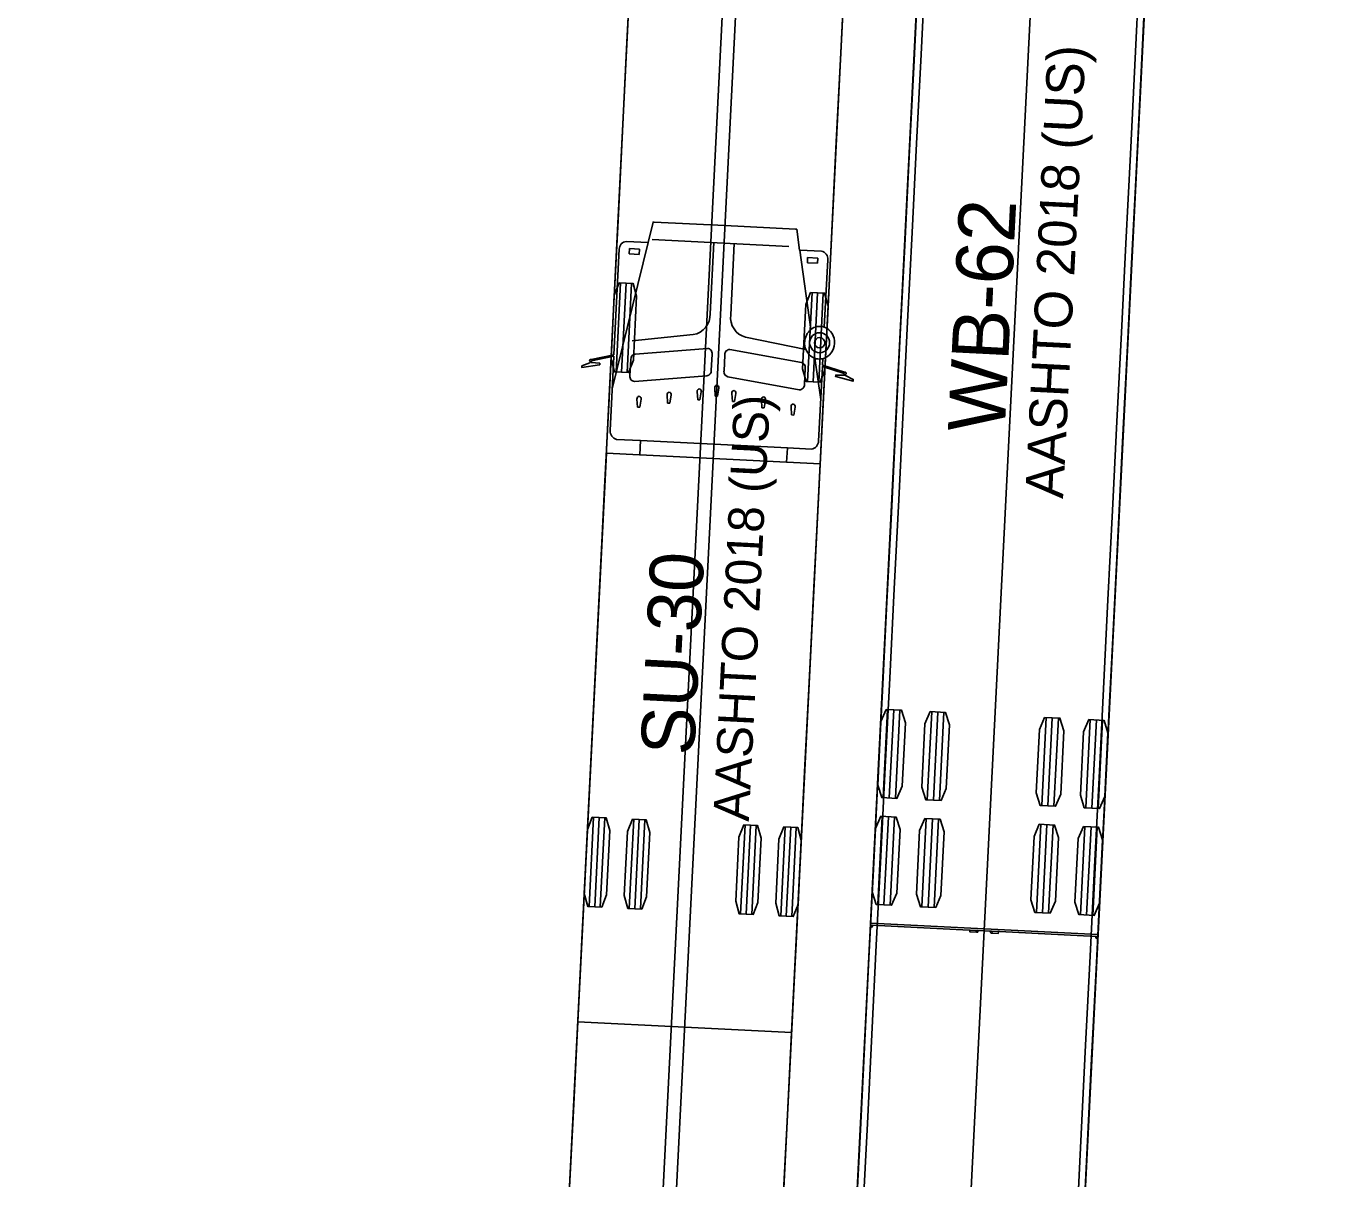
# Model space of a CAD drawing. Extents: x 260275 to 261282, y 610916 to 614143.
# Drawn here: x 261035.48 to 261084.72, y 612370.96 to 612414.03 of the extents above; entities that cross this region are included whole.
import ezdxf

# ---------------------------------------------------------------- set-up
doc = ezdxf.new("R2010")
doc.units = 0
doc.layers.add('GE_X_Alignment', color=7, linetype='Continuous')
doc.layers.add('TopoDOT_Transients', color=7, linetype='Continuous')

msp = doc.modelspace()

# ---------------------------------------------------------------- linework, layer by layer
at = {"layer": 'GE_X_Alignment'}
msp.add_line((260986.249, 610915.954), (261148.276, 614142.838), dxfattribs=at)
at = {"layer": 'TopoDOT_Transients'}
for p, q in [((261059.045, 612136.423), (261081.046, 612574.591)), ((261048.059, 612136.974), (261068.197, 612538.052)), ((261057.385, 612400.477), (261058.725, 612405.944)), ((261058.014, 612405.523), (261058.024, 612405.717)), ((261058.024, 612405.717), (261058.402, 612405.698)), ((261058.402, 612405.698), (261058.392, 612405.504)), ((261063.98, 612405.803), (261058.881, 612406.059)), ((261061.181, 612405.944), (261061.047, 612403.279)), ((261061.946, 612405.905), (261061.812, 612403.241)), ((261058.392, 612405.504), (261058.014, 612405.523)), ((261064.807, 612402.694), (261064.389, 612405.66)), ((261064.686, 612405.383), (261064.676, 612405.189)), ((261064.676, 612405.189), (261065.054, 612405.17)), ((261065.064, 612405.364), (261064.686, 612405.383)), ((261065.054, 612405.17), (261065.064, 612405.364)), ((261065.31, 612402.785), (261065.437, 612405.304)), ((261057.692, 612404.439), (261057.525, 612401.11)), ((261057.9, 612404.428), (261057.733, 612401.099)), ((261058.108, 612404.418), (261057.941, 612401.089)), ((261064.85, 612404.079), (261064.683, 612400.75)), ((261065.058, 612404.069), (261064.891, 612400.74)), ((261065.266, 612404.059), (261065.099, 612400.729)), ((261060.409, 612402.503), (261058.13, 612402.272)), ((261062.369, 612402.405), (261064.625, 612401.944)), ((261058.237, 612401.773), (261060.946, 612401.989)), ((261061.117, 612401.778), (261061.086, 612401.162)), ((261061.592, 612401.754), (261061.561, 612401.138)), ((261064.457, 612401.461), (261061.783, 612401.947)), ((261058.045, 612400.963), (261058.075, 612401.579)), ((261064.567, 612400.635), (261064.598, 612401.251)), ((261065.175, 612400.085), (261064.959, 612401.619)), ((261060.924, 612400.968), (261058.216, 612400.752)), ((261061.702, 612400.929), (261064.376, 612400.443)), ((261060.579, 612400.073), (261060.558, 612400.374)), ((261060.712, 612400.366), (261060.661, 612400.069)), ((261061.235, 612400.208), (261061.214, 612400.509)), ((261061.368, 612400.502), (261061.317, 612400.204)), ((261061.874, 612400.008), (261061.853, 612400.309)), ((261062.007, 612400.301), (261061.956, 612400.004)), ((261058.328, 612399.793), (261058.307, 612400.094)), ((261058.41, 612399.788), (261058.328, 612399.793)), ((261058.461, 612400.086), (261058.41, 612399.788)), ((261059.454, 612399.947), (261059.433, 612400.262)), ((261059.536, 612399.943), (261059.454, 612399.947)), ((261059.587, 612400.254), (261059.536, 612399.943)), ((261060.661, 612400.069), (261060.579, 612400.073)), ((261061.317, 612400.204), (261061.235, 612400.208)), ((261061.956, 612400.004), (261061.874, 612400.008)), ((261062.98, 612399.77), (261062.96, 612400.071)), ((261063.063, 612399.765), (261062.98, 612399.77)), ((261063.114, 612400.063), (261063.063, 612399.765)), ((261064.086, 612399.503), (261064.065, 612399.805)), ((261064.219, 612399.797), (261064.168, 612399.499)), ((261064.168, 612399.499), (261064.086, 612399.503)), ((261063.928, 612398.27), (261058.443, 612398.545)), ((261063.902, 612397.739), (261058.417, 612398.014)), ((261067.676, 612388.494), (261067.51, 612385.199)), ((261067.905, 612388.483), (261067.739, 612385.187)), ((261068.134, 612388.471), (261067.968, 612385.176)), ((261069.324, 612388.412), (261069.158, 612385.116)), ((261069.553, 612388.4), (261069.387, 612385.104)), ((261069.782, 612388.389), (261069.616, 612385.093)), ((261073.602, 612388.197), (261073.436, 612384.901)), ((261073.831, 612388.185), (261073.665, 612384.89)), ((261074.06, 612388.174), (261073.894, 612384.878)), ((261075.25, 612388.114), (261075.084, 612384.818)), ((261075.479, 612388.103), (261075.313, 612384.807)), ((261075.707, 612388.091), (261075.542, 612384.795)), ((261056.689, 612384.464), (261056.522, 612381.135)), ((261056.897, 612384.454), (261056.73, 612381.124)), ((261057.105, 612384.443), (261056.938, 612381.114)), ((261058.187, 612384.389), (261058.02, 612381.06)), ((261058.395, 612384.378), (261058.228, 612381.049)), ((261058.603, 612384.368), (261058.436, 612381.039)), ((261062.349, 612384.18), (261062.182, 612380.851)), ((261062.557, 612384.169), (261062.39, 612380.84)), ((261062.765, 612384.159), (261062.598, 612380.83)), ((261063.847, 612384.105), (261063.68, 612380.775)), ((261064.055, 612384.094), (261063.888, 612380.765)), ((261064.263, 612384.084), (261064.096, 612380.755)), ((261067.475, 612384.499), (261067.31, 612381.204)), ((261067.704, 612384.488), (261067.539, 612381.192)), ((261067.933, 612384.476), (261067.768, 612381.181)), ((261069.123, 612384.417), (261068.958, 612381.121)), ((261069.352, 612384.405), (261069.187, 612381.109)), ((261069.581, 612384.394), (261069.416, 612381.098)), ((261073.401, 612384.202), (261073.236, 612380.906)), ((261073.63, 612384.19), (261073.465, 612380.895)), ((261073.859, 612384.179), (261073.693, 612380.883)), ((261075.049, 612384.119), (261074.884, 612380.823)), ((261075.278, 612384.108), (261075.113, 612380.812)), ((261075.507, 612384.096), (261075.341, 612380.8)), ((261075.535, 612380.081), (261067.045, 612380.507)), ((261071.021, 612380.237), (261070.756, 612380.25)), ((261071.027, 612380.236), (261071.55, 612380.21)), ((261071.287, 612380.224), (261071.29, 612380.294)), ((261071.817, 612380.197), (261071.552, 612380.21))]:
    msp.add_line(p, q, dxfattribs=at)
for points in [[(261051.548, 612071.863), (261074.206, 612523.277)], [(261082.631, 612521.243), (261060.03, 612071.291)], [(261042.767, 612111.356), (261063.016, 612514.614)], [(261070.923, 612512.551), (261050.75, 612110.806)], [(261075.509, 612380.012), (261075.531, 612380.01), (261077.935, 612427.88), (261073.69, 612428.093), (261069.445, 612428.306), (261067.042, 612380.437), (261067.064, 612380.436)], [(261055.762, 612370.162), (261055.93, 612373.49), (261056.097, 612376.819), (261056.264, 612380.147), (261056.431, 612383.476), (261056.598, 612386.804), (261056.765, 612390.132), (261056.932, 612393.461), (261057.099, 612396.789), (261057.267, 612400.118), (261057.434, 612403.446), (261057.601, 612406.775), (261057.768, 612410.103), (261057.935, 612413.432), (261058.102, 612416.76)], [(261055.763, 612370.166), (261055.93, 612373.494), (261056.097, 612376.823), (261056.264, 612380.151), (261056.431, 612383.48), (261056.598, 612386.808), (261056.765, 612390.137), (261056.933, 612393.465), (261057.1, 612396.793), (261057.267, 612400.122), (261057.434, 612403.45), (261057.601, 612406.779), (261057.768, 612410.107), (261057.935, 612413.436), (261058.102, 612416.764)], [(261063.752, 612369.761), (261063.919, 612373.089), (261064.087, 612376.417), (261064.254, 612379.746), (261064.421, 612383.074), (261064.588, 612386.403), (261064.755, 612389.731), (261064.922, 612393.06), (261065.089, 612396.388), (261065.256, 612399.717), (261065.424, 612403.045), (261065.591, 612406.373), (261065.758, 612409.702), (261065.925, 612413.03), (261066.092, 612416.359)], [(261063.753, 612369.765), (261063.92, 612373.093), (261064.087, 612376.422), (261064.254, 612379.75), (261064.421, 612383.079), (261064.588, 612386.407), (261064.755, 612389.735), (261064.922, 612393.064), (261065.09, 612396.392), (261065.257, 612399.721), (261065.424, 612403.049), (261065.591, 612406.378), (261065.758, 612409.706), (261065.925, 612413.035), (261066.092, 612416.363)], [(261066.753, 612369.691), (261066.92, 612373.021), (261067.087, 612376.35), (261067.254, 612379.68), (261067.421, 612383.009), (261067.589, 612386.339), (261067.756, 612389.668), (261067.923, 612392.998), (261068.09, 612396.328), (261068.257, 612399.657), (261068.424, 612402.987), (261068.592, 612406.316), (261068.759, 612409.646), (261068.926, 612412.975), (261069.093, 612416.305)], [(261066.478, 612369.212), (261066.645, 612372.541), (261066.813, 612375.871), (261066.98, 612379.2), (261067.147, 612382.53), (261067.314, 612385.859), (261067.481, 612389.189), (261067.649, 612392.518), (261067.816, 612395.848), (261067.983, 612399.178), (261068.15, 612402.507), (261068.317, 612405.837), (261068.484, 612409.166), (261068.652, 612412.496), (261068.819, 612415.825)], [(261074.743, 612369.29), (261074.91, 612372.62), (261075.077, 612375.949), (261075.244, 612379.279), (261075.411, 612382.608), (261075.578, 612385.938), (261075.746, 612389.267), (261075.913, 612392.597), (261076.08, 612395.926), (261076.247, 612399.256), (261076.414, 612402.585), (261076.582, 612405.915), (261076.749, 612409.245), (261076.916, 612412.574), (261077.083, 612415.904)], [(261074.968, 612368.785), (261075.135, 612372.115), (261075.302, 612375.444), (261075.469, 612378.774), (261075.636, 612382.104), (261075.803, 612385.433), (261075.971, 612388.763), (261076.138, 612392.092), (261076.305, 612395.422), (261076.472, 612398.751), (261076.639, 612402.081), (261076.807, 612405.41), (261076.974, 612408.74), (261077.141, 612412.069), (261077.308, 612415.399)], [(261065.199, 612405.619), (261064.392, 612405.66), (261064.388, 612405.664), (261064.278, 612406.442), (261064.236, 612406.446), (261061.596, 612406.579), (261058.956, 612406.712), (261058.913, 612406.712), (261058.726, 612405.949), (261058.722, 612405.944), (261057.915, 612405.985)], [(261057.647, 612405.695), (261057.449, 612401.767), (261057.442, 612401.755), (261056.6, 612401.571), (261056.599, 612401.571)], [(261056.555, 612401.5), (261056.552, 612401.453), (261056.552, 612401.452), (261056.251, 612401.336), (261056.248, 612401.271), (261056.25, 612401.271), (261056.913, 612401.377), (261056.916, 612401.378), (261056.918, 612401.434), (261056.916, 612401.434), (261056.599, 612401.458), (261056.599, 612401.459), (261056.602, 612401.503)], [(261056.614, 612401.523), (261056.614, 612401.523), (261057.441, 612401.701), (261057.446, 612401.689), (261057.306, 612398.918)], [(261065.097, 612398.527), (261065.236, 612401.298), (261065.241, 612401.309), (261066.046, 612401.049), (261066.047, 612401.049)], [(261066.066, 612401.096), (261066.065, 612401.096), (261065.246, 612401.363), (261065.24, 612401.376), (261065.251, 612401.603)], [(261066.057, 612401.028), (261066.055, 612400.984), (261066.055, 612400.984), (261065.737, 612400.991), (261065.735, 612400.991), (261065.732, 612400.935), (261065.735, 612400.934), (261066.383, 612400.762), (261066.386, 612400.762), (261066.389, 612400.827), (261066.101, 612400.973), (261066.101, 612400.973), (261066.103, 612401.021)], [(261057.545, 612398.59), (261058.44, 612398.545), (261058.443, 612398.541), (261058.417, 612398.015), (261058.406, 612398.015), (261057.164, 612398.077), (261056.097, 612376.817), (261060.092, 612376.617), (261064.087, 612376.416), (261065.154, 612397.676), (261063.913, 612397.738), (261063.902, 612397.74), (261063.928, 612398.266), (261063.931, 612398.27), (261064.826, 612398.225)], [(261067.088, 612380.434), (261067.089, 612380.434), (261070.72, 612380.252), (261070.756, 612380.25), (261070.752, 612380.18), (261070.754, 612380.18), (261071.02, 612380.166)], [(261071.546, 612380.14), (261071.812, 612380.126), (261071.814, 612380.127), (261071.817, 612380.197), (261071.853, 612380.195), (261075.484, 612380.013), (261075.485, 612380.013)]]:
    msp.add_lwpolyline(points, dxfattribs=at)
for points in [[(261057.641, 612404.441), (261058.16, 612404.415), (261058.293, 612403.941), (261058.173, 612401.544), (261057.993, 612401.086), (261057.473, 612401.112), (261057.34, 612401.586), (261057.461, 612403.983)], [(261064.798, 612404.082), (261065.318, 612404.056), (261065.451, 612403.582), (261065.33, 612401.185), (261065.15, 612400.727), (261064.631, 612400.753), (261064.498, 612401.227), (261064.618, 612403.624)], [(261067.619, 612388.497), (261068.19, 612388.469), (261068.339, 612387.999), (261068.22, 612385.626), (261068.025, 612385.173), (261067.454, 612385.201), (261067.305, 612385.671), (261067.424, 612388.044)], [(261069.267, 612388.415), (261069.838, 612388.386), (261069.987, 612387.916), (261069.868, 612385.543), (261069.673, 612385.09), (261069.102, 612385.119), (261068.953, 612385.589), (261069.072, 612387.962)], [(261073.545, 612388.2), (261074.116, 612388.171), (261074.265, 612387.701), (261074.146, 612385.328), (261073.951, 612384.875), (261073.38, 612384.904), (261073.231, 612385.374), (261073.35, 612387.747)], [(261075.193, 612388.117), (261075.764, 612388.088), (261075.913, 612387.618), (261075.794, 612385.245), (261075.599, 612384.792), (261075.027, 612384.821), (261074.879, 612385.291), (261074.998, 612387.664)], [(261056.638, 612384.467), (261057.157, 612384.44), (261057.29, 612383.967), (261057.17, 612381.57), (261056.99, 612381.111), (261056.47, 612381.137), (261056.337, 612381.611), (261056.458, 612384.008)], [(261058.136, 612384.391), (261058.655, 612384.365), (261058.788, 612383.891), (261058.668, 612381.494), (261058.488, 612381.036), (261057.969, 612381.062), (261057.835, 612381.536), (261057.956, 612383.933)], [(261062.297, 612384.182), (261062.816, 612384.156), (261062.95, 612383.682), (261062.829, 612381.285), (261062.649, 612380.827), (261062.13, 612380.853), (261061.997, 612381.327), (261062.117, 612383.724)], [(261063.795, 612384.107), (261064.315, 612384.081), (261064.448, 612383.607), (261064.327, 612381.21), (261064.147, 612380.752), (261063.628, 612380.778), (261063.495, 612381.252), (261063.615, 612383.649)], [(261067.419, 612384.502), (261067.99, 612384.474), (261068.139, 612384.004), (261068.02, 612381.631), (261067.824, 612381.178), (261067.253, 612381.206), (261067.104, 612381.677), (261067.223, 612384.05)], [(261069.067, 612384.42), (261069.638, 612384.391), (261069.787, 612383.921), (261069.668, 612381.548), (261069.472, 612381.095), (261068.901, 612381.124), (261068.752, 612381.594), (261068.871, 612383.967)], [(261073.344, 612384.205), (261073.916, 612384.176), (261074.065, 612383.706), (261073.946, 612381.333), (261073.75, 612380.88), (261073.179, 612380.909), (261073.03, 612381.379), (261073.149, 612383.752)], [(261074.992, 612384.122), (261075.564, 612384.093), (261075.713, 612383.623), (261075.593, 612381.25), (261075.398, 612380.797), (261074.827, 612380.826), (261074.678, 612381.296), (261074.797, 612383.669)]]:
    msp.add_lwpolyline(points, close=True, dxfattribs=at)
for centre, radius in [((261065.136, 612402.201), 0.374), ((261065.136, 612402.201), 0.193), ((261067.074, 612380.401), 0.0266), ((261075.495, 612379.978), 0.0266)]:
    msp.add_circle(centre, radius, dxfattribs=at)
for centre, radius, start, end in [((261057.928, 612405.703), 0.282, 92.6739, 181.7533), ((261065.158, 612405.34), 0.282, 352.4977, 81.5771), ((261060.274, 612403.264), 0.773, 280.016, 1.1001), ((261062.579, 612403.148), 0.773, 173.1509, 254.235), ((261065.14, 612402.287), 0.526, 71.0707, 129.3167), ((261065.069, 612402.205), 0.628, 286.8788, 67.3705), ((261065.205, 612402.206), 0.629, 129.1711, 177.8604), ((261058.268, 612401.583), 0.193, 99.2679, 181.1824), ((261060.934, 612401.805), 0.184, 351.6672, 86.5274), ((261061.776, 612401.763), 0.184, 87.7236, 182.5838), ((261065.204, 612402.191), 0.63, 176.4803, 228.8831), ((261056.578, 612401.535), 0.0418, 59.6174, 236.6324), ((261056.572, 612401.535), 0.0434, 312.5392, 343.212), ((261064.407, 612401.275), 0.193, 353.0686, 74.9831), ((261065.132, 612402.114), 0.524, 229.3845, 283.1846), ((261058.227, 612400.936), 0.184, 171.6617, 266.5329), ((261060.893, 612401.158), 0.193, 279.263, 1.1873), ((261061.752, 612401.115), 0.193, 173.0637, 254.988), ((261066.089, 612401.057), 0.0434, 191.039, 221.7118), ((261066.083, 612401.058), 0.0418, 297.6187, 114.6336), ((261059.523, 612400.262), 0.091, 94.6451, 188.8089), ((261059.499, 612400.263), 0.0909, 345.4064, 79.6416), ((261060.648, 612400.388), 0.091, 94.6451, 188.8089), ((261060.624, 612400.389), 0.0909, 345.4064, 79.6416), ((261061.304, 612400.523), 0.091, 94.6451, 188.8089), ((261061.28, 612400.525), 0.091, 345.4421, 79.6059), ((261061.943, 612400.323), 0.0909, 94.6094, 188.8446), ((261061.919, 612400.324), 0.091, 345.4421, 79.6059), ((261064.383, 612400.627), 0.184, 267.7181, 2.5893), ((261058.397, 612400.108), 0.091, 94.6451, 188.8089), ((261058.373, 612400.109), 0.0909, 345.4064, 79.6416), ((261063.049, 612400.085), 0.0909, 94.6094, 188.8446), ((261063.026, 612400.086), 0.091, 345.4421, 79.6059), ((261064.155, 612399.819), 0.0909, 94.6094, 188.8446), ((261064.131, 612399.82), 0.091, 345.4421, 79.6059), ((261057.629, 612398.902), 0.323, 177.1255, 254.9739), ((261064.774, 612398.543), 0.323, 279.2771, 357.1255), ((261067.074, 612380.401), 0.0363, 106.2023, 67.3649), ((261071.021, 612380.202), 0.0352, 86.913, 269.5524), ((261071.022, 612380.202), 0.0352, 267.1411, 87.7276), ((261071.548, 612380.175), 0.0352, 86.5234, 267.1099), ((261071.548, 612380.175), 0.0354, 271.417, 83.6025), ((261075.495, 612379.978), 0.0363, 106.8861, 68.0487)]:
    msp.add_arc(centre, radius, start, end, dxfattribs=at)

# ---------------------------------------------------------------- texts
for s, height, p in [('AASHTO 2018 (US)', 1.41667, (261074.232, 612396.36)), ('WB-62', 2.125, (261072.05, 612398.826)), ('AASHTO 2018 (US)', 1.33333, (261062.486, 612384.292)), ('SU-30', 2, (261060.44, 612386.755))]:
    msp.add_text(s, height=height, rotation=87.1255, dxfattribs=at).set_placement(p)

doc.saveas('drawing.dxf')
